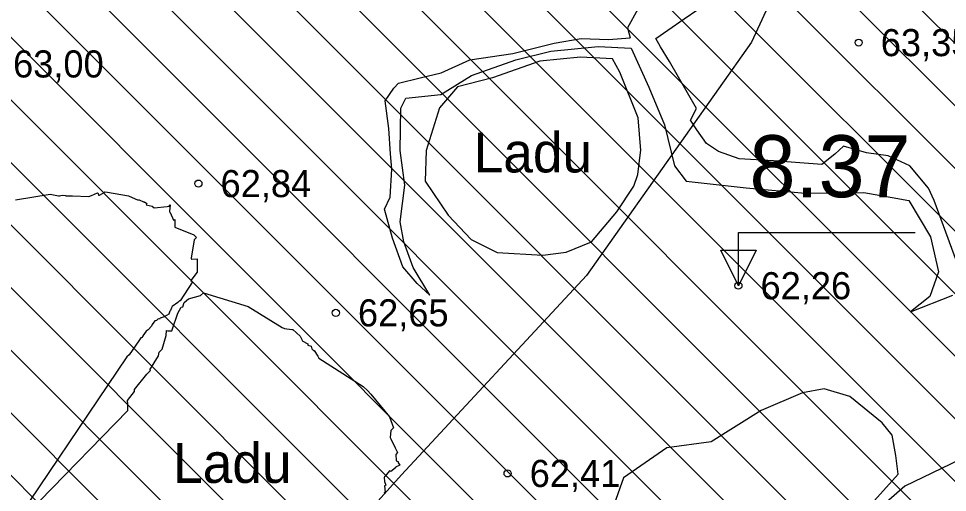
# Model space of a CAD drawing. Extents: x 532503 to 539665, y 6557663 to 6561526.
# Drawn here: x 535181.8 to 535265.8, y 6559700.3 to 6559743.1 of the extents above; entities that cross this region are included whole.
import ezdxf

# ---------------------------------------------------------------- set-up
doc = ezdxf.new("R2010")
doc.units = 0
for name, color, linetype in [('HALJASTUS', 7, 'Continuous'), ('jääkpaksus', 7, 'Continuous'), ('Kaevandatud ala', 7, 'Continuous'), ('KORGUS-EH2000', 7, 'Continuous'), ('Lamami horisontaal_EH2000', 7, 'Continuous'), ('RELJEEF', 7, 'Continuous')]:
    doc.layers.add(name, color=color, linetype=linetype)

msp = doc.modelspace()

# ---------------------------------------------------------------- linework, layer by layer
at = {"layer": 'jääkpaksus'}
msp.add_lwpolyline([(535246.867, 6559718.966), (535246.867, 6559723.766), (535262.867, 6559723.766)], dxfattribs=at)
msp.add_lwpolyline([(535246.867, 6559718.966), (535245.267, 6559722.166), (535248.467, 6559722.166)], close=True, dxfattribs=at)
at = {"layer": 'Kaevandatud ala'}
for p, q in [((535207.308, 6559788.703), (535303.947, 6559692.064)), ((535197.58, 6559787.117), (535297.533, 6559687.164)), ((535202.943, 6559787.412), (535300.74, 6559689.614)), ((535192.612, 6559786.429), (535294.326, 6559684.715)), ((535189.019, 6559784.365), (535291.119, 6559682.265)), ((535186.572, 6559781.155), (535287.911, 6559679.815)), ((535184.457, 6559777.613), (535284.704, 6559677.366)), ((535182.417, 6559773.996), (535281.497, 6559674.916)), ((535180.416, 6559770.341), (535278.29, 6559672.466)), ((535232.379, 6559769.288), (535307.155, 6559694.513)), ((535166.863, 6559766.922), (535268.668, 6559665.117)), ((535178.444, 6559766.656), (535275.083, 6559670.017)), ((535241.599, 6559765.726), (535310.362, 6559696.963)), ((535176.48, 6559762.963), (535271.876, 6559667.567)), ((535171.315, 6559756.814), (535265.461, 6559662.668)), ((535127.862, 6559755.011), (535209.229, 6559673.645)), ((535150.863, 6559754.638), (535252.632, 6559652.869)), ((535156.535, 6559754.623), (535255.84, 6559655.319)), ((535134.478, 6559754.053), (535221.942, 6559666.589)), ((535140.666, 6559753.522), (535234.654, 6559659.534)), ((535145.883, 6559753.962), (535247.366, 6559652.478)), ((535168.701, 6559753.77), (535262.254, 6559660.218)), ((535163.688, 6559753.127), (535259.047, 6559657.768))]:
    msp.add_line(p, q, dxfattribs=at)
at = {"layer": 'KORGUS-EH2000'}
for centre in [(535257.741, 6559740.94), (535198.026, 6559728.197), (535246.867, 6559718.966), (535210.454, 6559716.511), (535225.988, 6559701.996)]:
    msp.add_circle(centre, 0.32, dxfattribs=at)
at = {"layer": 'Lamami horisontaal_EH2000'}
msp.add_lwpolyline([(535264.802, 6559805.462), (535263.458, 6559783.966), (535257.965, 6559762.413), (535256.203, 6559758.595), (535248.061, 6559740.976), (535233.126, 6559719.895), (535216.403, 6559701.861), (535211.903, 6559696.864), (535200.273, 6559686.281), (535185.985, 6559675.93), (535185.524, 6559675.832), (535181.605, 6559675.144), (535168.436, 6559674.25), (535164.517, 6559673.671), (535150.622, 6559670.627), (535141.664, 6559668.512), (535132.808, 6559666.369), (535114.994, 6559660.822), (535101.099, 6559654.5), (535097.703, 6559653.447), (535096.703, 6559652.879), (535096.18, 6559652.727), (535083.285, 6559645.964)], dxfattribs=at)
at = {"layer": 'RELJEEF'}
for points in [[(535250.546, 6559758.112), (535252.183, 6559757.897), (535253.022, 6559757.927), (535254.047, 6559759.847), (535255.329, 6559760.614), (535257.357, 6559758.557), (535255.351, 6559755.964), (535251.381, 6559752.781), (535247.846, 6559751.072), (535244.602, 6559749.093), (535241.885, 6559746.688), (535239.295, 6559744.5), (535237.783, 6559743.958), (535236.825, 6559742.288), (535237.063, 6559741.384)], [(535250.546, 6559758.112), (535253.022, 6559757.927), (535254.047, 6559759.847), (535255.329, 6559760.614), (535257.357, 6559758.557), (535255.351, 6559755.964), (535251.381, 6559752.781), (535247.138, 6559750.64), (535245.493, 6559749.669), (535244.709, 6559749.158), (535239.562, 6559744.725), (535237.783, 6559743.958), (535236.825, 6559742.288), (535237.063, 6559741.384)], [(535267.229, 6559719.456), (535264.558, 6559726.667), (535264.056, 6559727.794), (535262.375, 6559729.806), (535260.398, 6559730.713), (535258.464, 6559730.979), (535256.367, 6559731.594), (535255.586, 6559730.862), (535254.415, 6559729.916), (535250.043, 6559730.251), (535246.929, 6559730.446), (535245.051, 6559731.086), (535243.992, 6559731.811), (535243.105, 6559733.048), (535242.527, 6559733.943), (535243.065, 6559734.998), (535240.646, 6559739.241), (535239.819, 6559740.552), (535239.387, 6559741.306), (535240.472, 6559742.054), (535241.961, 6559743.083), (535243.202, 6559743.945)], [(535218.952, 6559718.115), (535217.8, 6559719.16), (535216.525, 6559720.685), (535215.594, 6559723.27), (535214.868, 6559725.88), (535215.377, 6559726.958), (535215.506, 6559729.49), (535215.403, 6559730.886), (535215.242, 6559733.172), (535214.903, 6559735.667), (535215.688, 6559736.832), (535216.111, 6559737.278), (535218.075, 6559737.755), (535219.971, 6559738.197), (535222.564, 6559739.396), (535226.461, 6559739.95), (535230.211, 6559740.905), (535232.636, 6559741.317), (535235.109, 6559741.211), (535237.063, 6559741.384)], [(535218.952, 6559718.115), (535217.447, 6559720.597), (535216.608, 6559722.941), (535216.279, 6559724.728), (535216.699, 6559728.041), (535216.288, 6559731.193), (535216.335, 6559735.023), (535216.783, 6559735.917), (535219.961, 6559736.264), (535222.726, 6559737.981), (535226.732, 6559739.389), (535229.888, 6559740.164), (535234.186, 6559740.583), (535237.173, 6559740.446), (535238.766, 6559736.922), (535240.191, 6559733.495), (535241.08, 6559729.811), (535242.141, 6559728.43), (535247.557, 6559727.821), (535252.892, 6559727.328), (535258.2, 6559727.403), (535260.774, 6559726.93), (535262.273, 6559726.667), (535264.234, 6559723.39), (535264.968, 6559720.207), (535264.183, 6559717.998), (535262.431, 6559716.614)], [(535218.952, 6559718.115), (535217.447, 6559720.597), (535216.608, 6559722.941), (535216.279, 6559724.728), (535216.699, 6559728.041), (535216.288, 6559731.193), (535216.335, 6559735.023), (535216.783, 6559735.917), (535219.961, 6559736.264), (535222.726, 6559737.981), (535226.732, 6559739.389), (535229.888, 6559740.164), (535234.186, 6559740.583), (535237.173, 6559740.446), (535238.766, 6559736.922), (535240.191, 6559733.495), (535241.08, 6559729.811), (535242.141, 6559728.43), (535247.557, 6559727.821), (535252.892, 6559727.328), (535258.2, 6559727.403), (535260.774, 6559726.93), (535262.273, 6559726.667), (535264.234, 6559723.39), (535264.968, 6559720.207), (535264.183, 6559717.998), (535262.431, 6559716.614)], [(535238.055, 6559731.195), (535237.801, 6559734.131), (535236.139, 6559738.269), (535235.481, 6559739.464), (535232.595, 6559739.624), (535228.897, 6559739.257), (535224.623, 6559737.751), (535221.455, 6559736.958), (535219.823, 6559735.037), (535218.628, 6559731.189), (535218.535, 6559728.424), (535220.614, 6559725.347), (535222.688, 6559723.134), (535225.05, 6559721.957), (535229.166, 6559721.719), (535231.288, 6559722.012), (535233.579, 6559722.939), (535235.857, 6559725.645), (535237.409, 6559727.973), (535237.767, 6559729.004), (535238.051, 6559731.248)], [(535238.055, 6559731.195), (535237.801, 6559734.131), (535236.139, 6559738.269), (535235.481, 6559739.464), (535232.595, 6559739.624), (535228.897, 6559739.257), (535224.623, 6559737.751), (535221.455, 6559736.958), (535219.823, 6559735.037), (535218.628, 6559731.189), (535218.535, 6559728.424), (535220.614, 6559725.347), (535222.688, 6559723.134), (535225.05, 6559721.957), (535229.166, 6559721.719), (535231.288, 6559722.012), (535233.579, 6559722.939), (535235.857, 6559725.645), (535237.409, 6559727.973), (535237.767, 6559729.004), (535238.051, 6559731.248)], [(535181.468, 6559726.721), (535184.625, 6559727.252), (535185.37, 6559727.093), (535185.371, 6559727.077), (535185.447, 6559727.086), (535185.706, 6559727.158), (535185.991, 6559727.121), (535186.039, 6559727.086), (535186.625, 6559727.102), (535188.114, 6559727.028), (535188.362, 6559727.119), (535188.888, 6559727.362), (535188.947, 6559727.31), (535188.983, 6559727.162), (535189.075, 6559727.145), (535189.511, 6559727.402), (535189.562, 6559727.463), (535189.793, 6559727.421), (535191.715, 6559727.099), (535192.567, 6559726.691), (535192.619, 6559726.751), (535193.107, 6559726.521), (535193.14, 6559726.56), (535193.368, 6559726.406), (535193.312, 6559726.281), (535193.846, 6559726.156), (535194.033, 6559726.019), (535195.202, 6559726.135), (535195.377, 6559726.16), (535195.477, 6559726.27), (535195.47, 6559726.173), (535195.436, 6559726.048), (535195.401, 6559725.637), (535195.462, 6559725.585), (535195.77, 6559724.89), (535195.9, 6559724.938), (535195.896, 6559724.652), (535195.901, 6559724.596), (535195.888, 6559724.261), (535197.611, 6559723.576), (535197.854, 6559723.308), (535197.641, 6559723.123), (535197.357, 6559721.454), (535197.392, 6559721.376), (535197.912, 6559721.403), (535197.9, 6559720.202), (535197.327, 6559719.43), (535197.499, 6559719.326), (535196.378, 6559717.587), (535196.321, 6559717.584), (535196.159, 6559717.457), (535195.644, 6559717.072), (535195.592, 6559716.968), (535195.496, 6559716.73), (535195.444, 6559716.663), (535195.352, 6559716.391), (535194.935, 6559716.165), (535194.552, 6559716.025), (535194.549, 6559716.006), (535194.497, 6559715.944), (535194.386, 6559715.956), (535194.224, 6559715.829), (535194.082, 6559715.803), (535193.851, 6559715.454), (535193.778, 6559715.318), (535193.485, 6559714.971), (535193.31, 6559714.846), (535192.998, 6559714.434), (535193.011, 6559714.413), (535192.903, 6559714.298), (535192.829, 6559714.247), (535192.639, 6559713.993), (535191.753, 6559712.715), (535191.536, 6559712.526), (535180.118, 6559695.61)], [(535183.662, 6559699.492), (535191.649, 6559707.676), (535191.633, 6559708.249), (535191.609, 6559708.597), (535192.239, 6559709.408), (535192.229, 6559709.573), (535193.369, 6559710.979), (535193.684, 6559711.299), (535193.623, 6559711.348), (535194.413, 6559712.635), (535194.482, 6559712.972), (535194.724, 6559713.19), (535194.749, 6559713.228), (535195.117, 6559714.474), (535195.143, 6559714.923), (535195.259, 6559714.883), (535195.626, 6559714.885), (535195.663, 6559714.985), (535196.17, 6559716.49), (535196.474, 6559717.024), (535196.608, 6559717.067), (535196.727, 6559717.442), (535197.116, 6559717.764), (535198.214, 6559718.067), (535198.484, 6559718.309), (535202.523, 6559717.099), (535205.592, 6559715.182), (535205.82, 6559715.107), (535206.464, 6559714.992), (535206.578, 6559715), (535207.236, 6559714.392), (535207.373, 6559714.116), (535207.423, 6559713.976), (535207.922, 6559713.701), (535207.931, 6559713.583), (535208.224, 6559713.497), (535208.286, 6559713.27), (535208.437, 6559713.099), (535208.493, 6559713.104), (535208.827, 6559712.591), (535208.915, 6559712.405), (535212.93, 6559709.864), (535213.311, 6559709.491), (535213.627, 6559709.171), (535215.296, 6559707.126), (535215.665, 6559706.126), (535215.423, 6559705.872), (535215.36, 6559705.241), (535215.42, 6559705.134), (535215.814, 6559704.312), (535216.029, 6559703.876), (535215.873, 6559703.692), (535215.902, 6559703.178), (535215.909, 6559703.121), (535216.089, 6559703.078), (535216.057, 6559703.003), (535216.242, 6559702.738), (535215.853, 6559702.552), (535215.858, 6559702.495), (535215.438, 6559702.178), (535215.322, 6559702.226), (535214.895, 6559701.725), (535214.855, 6559701.734), (535214.82, 6559701.621), (535214.845, 6559701.261), (535214.975, 6559700.949), (535214.869, 6559700.884), (535214.909, 6559700.316), (535214.804, 6559700.252)], [(535262.431, 6559716.614), (535266.255, 6559718.103)], [(535261.315, 6559701.937), (535261.1, 6559703.611), (535260.762, 6559705.451), (535259.867, 6559706.561), (535256.955, 6559708.952), (535254.617, 6559709.631), (535252.667, 6559709.289), (535248.934, 6559707.696), (535244.391, 6559704.857), (535240.385, 6559704.311), (535236.478, 6559701.606), (535235.126, 6559697.784)], [(535261.315, 6559701.937), (535261.1, 6559703.611), (535260.762, 6559705.451), (535259.867, 6559706.561), (535256.955, 6559708.952), (535254.617, 6559709.631), (535252.667, 6559709.289), (535248.934, 6559707.696), (535244.391, 6559704.857), (535240.385, 6559704.311), (535236.478, 6559701.606), (535235.126, 6559697.784)], [(535270.979, 6559705.221), (535261.928, 6559700.833), (535257.824, 6559697.263), (535254.556, 6559694.425), (535252.708, 6559689.45), (535247.92, 6559687.545), (535244.474, 6559683.984), (535244.577, 6559680.494), (535246.247, 6559675.742), (535250.312, 6559668.654), (535254.096, 6559664.821), (535256.427, 6559664.093), (535264.001, 6559664.919), (535268.413, 6559666.649)], [(535270.979, 6559705.221), (535261.928, 6559700.833), (535257.824, 6559697.263), (535254.556, 6559694.425), (535252.708, 6559689.45), (535247.92, 6559687.545), (535244.474, 6559683.984), (535244.577, 6559680.494), (535246.247, 6559675.742), (535250.312, 6559668.654), (535254.096, 6559664.821), (535256.427, 6559664.093), (535264.001, 6559664.919), (535268.413, 6559666.649)], [(535254.556, 6559694.425), (535261.315, 6559701.937)], [(535254.556, 6559694.425), (535261.315, 6559701.937)]]:
    msp.add_lwpolyline(points, dxfattribs=at)

# ---------------------------------------------------------------- texts
at = {"layer": 'HALJASTUS'}
for p in [(535222.923, 6559729.206), (535195.738, 6559701.14)]:
    msp.add_text('Ladu', height=3.6, dxfattribs=at).set_placement(p)
at = {"layer": 'jääkpaksus'}
msp.add_text('8.37 ', height=5.6, dxfattribs=at).set_placement((535247.867, 6559726.966))
at = {"layer": 'KORGUS-EH2000'}
for s, p in [('63,35 ', (535259.741, 6559739.715)), ('63,00 ', (535181.261, 6559737.788)), ('62,84 ', (535200.026, 6559726.972)), ('62,26 ', (535248.867, 6559717.741)), ('62,65 ', (535212.454, 6559715.286)), ('62,41 ', (535227.988, 6559700.771))]:
    msp.add_text(s, height=2.45, dxfattribs=at).set_placement(p)

doc.saveas('drawing.dxf')
